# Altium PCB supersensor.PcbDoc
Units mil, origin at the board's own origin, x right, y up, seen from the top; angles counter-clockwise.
Board outline 1574.8 x 1574.8 mil, 2 copper layers (Top Layer, Bottom Layer); 41 components, 20 nets, 150 pads, 21 vias.
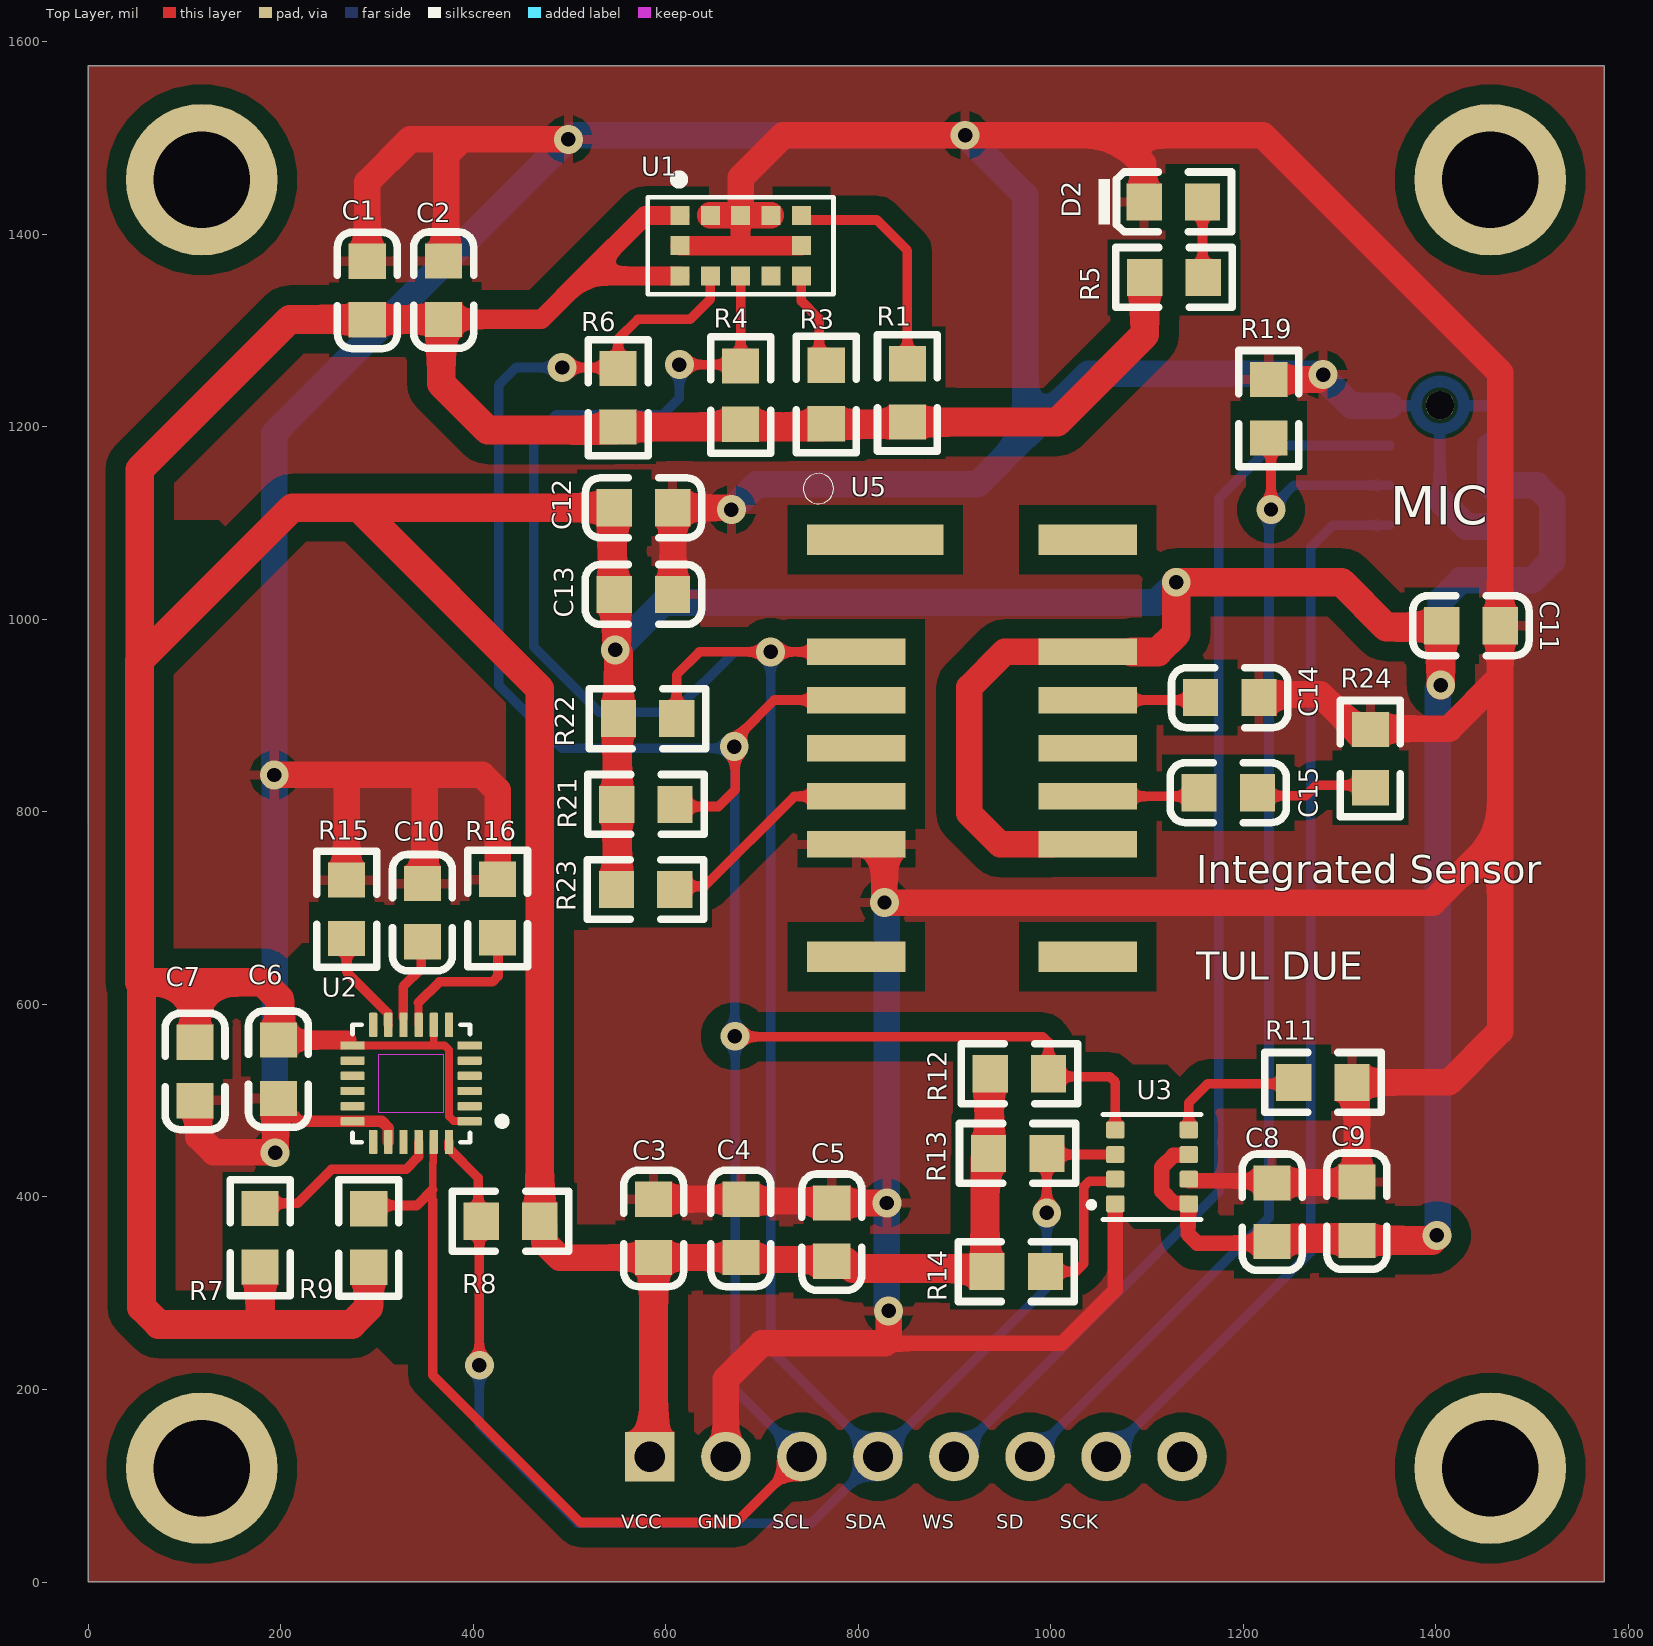
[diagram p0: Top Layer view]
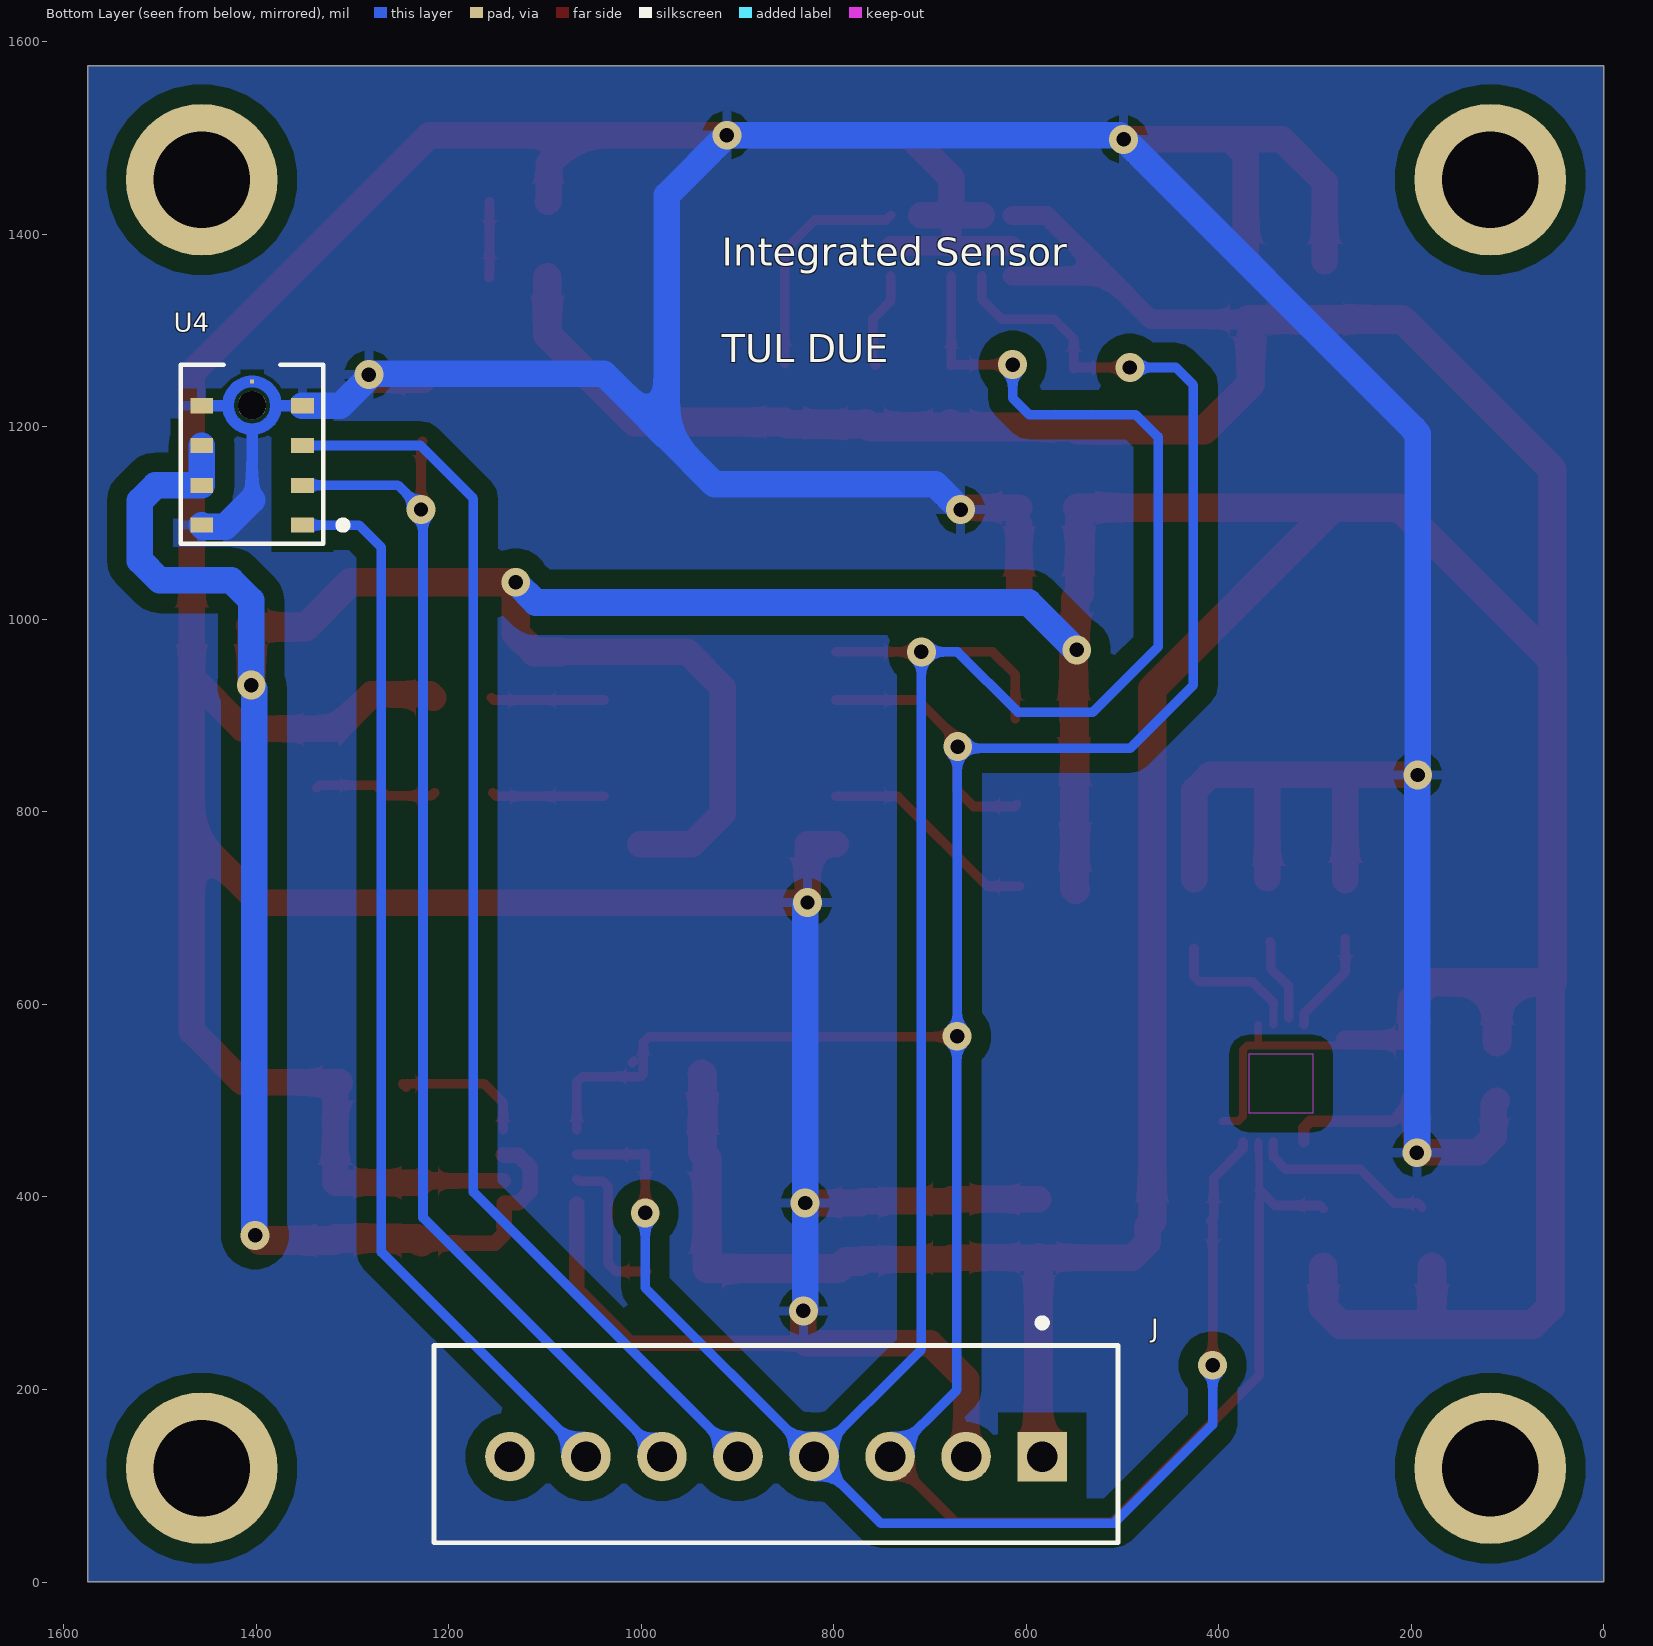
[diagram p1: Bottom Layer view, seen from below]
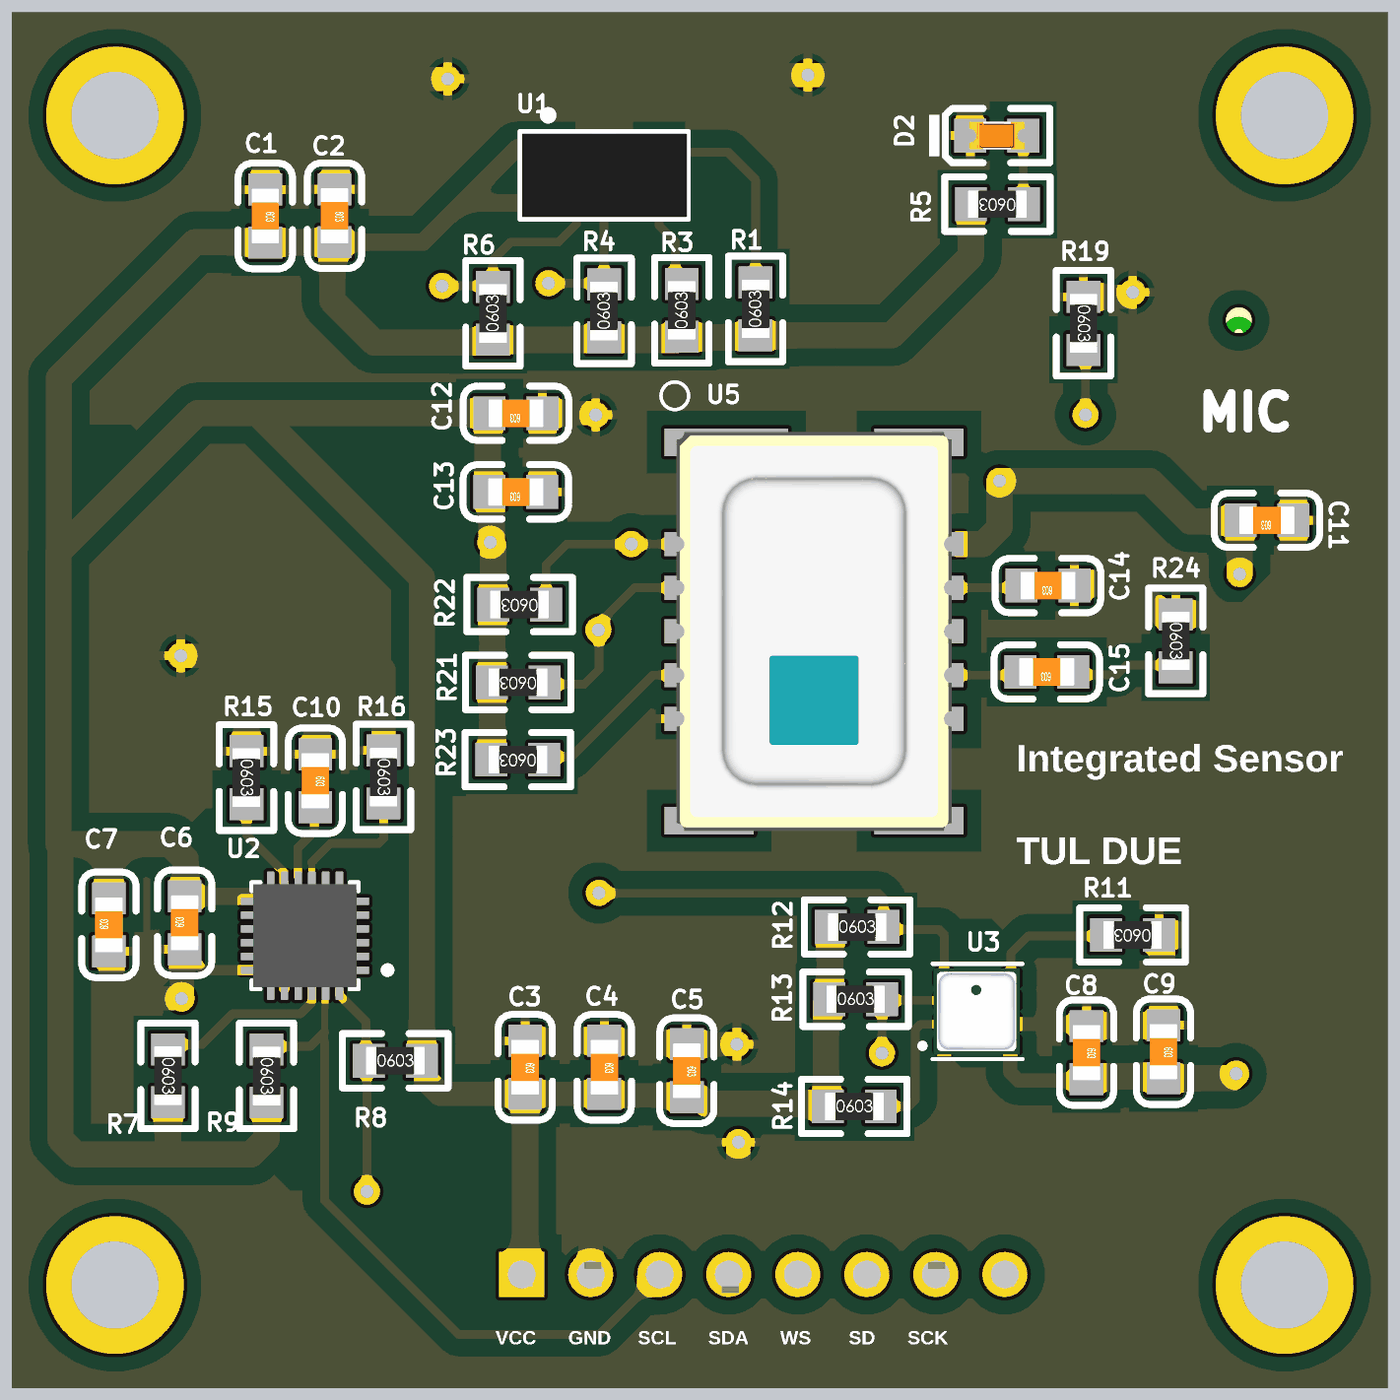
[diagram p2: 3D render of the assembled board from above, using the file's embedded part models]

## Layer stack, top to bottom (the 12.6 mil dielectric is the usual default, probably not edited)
Top Solder: solder mask 0.4, Solder Resist, Dk 3.5
Top Layer: signal copper 1.4
Dielectric 1: dielectric 12.6, FR-4, Dk 4.8
Bottom Layer: signal copper 1.4
Bottom Solder: solder mask 0.4, Solder Resist, Dk 3.5

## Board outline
0,0 0,1574.8 1574.8,1574.8 1574.8,0

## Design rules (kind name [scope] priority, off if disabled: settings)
Clearance [All] p1: gap=20 ignorepadtopadclearanceinfootprint=TRUE
PolygonConnect [All] p1: connectstyle=Relief reliefconductorwidth=10 reliefentries=4 polygonreliefangle="90 Angle" airgapwidth=10
RoutingVias [All] p1: holewidth=28 width=50 viastyle="Through Hole" minholewidth=28 minwidth=50 maxholewidth=28 maxwidth=50
SolderMaskExpansion [All] p1: expansion=4 istentingtop=FALSE
Width GND [InNet('GND')] p1: maxlimit=27.56 minlimit=27.56 preferedwidth=27.56 minimp=50.000000 maximp=50.000000 favimp=50.000000
Width VCC [InNet('VCC')] p2: maxlimit=30 minlimit=27.56 preferedwidth=30 toplayer_minwidth=30 bottomlayer_maxwidth=27.56 bottomlayer_prefwidth=27.56 minimp=50.000000 maximp=50.000000 favimp=50.000000
Width [All] p3: maxlimit=10 minlimit=10 preferedwidth=10
30 further rules are at their usual default settings.

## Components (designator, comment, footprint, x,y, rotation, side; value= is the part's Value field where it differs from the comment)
C1 "4.7uF" 0603_C 290.12,1341.62 r270 top
C2 "100nF" 0603_C 369.41,1341.91 r270 top
C3 "4.7uF" 0603_C 587.6,367.32 r270 top
C4 "10uF" 0603_C 678.15,367.32 r270 top
C5 "100nF" 0603_C 772.64,363.39 r270 top
C6 "10nF" 0603_C 197.83,532.68 r90 top
C7 "100nF" 0603_C 111.22,530.31 r90 top
C8 "1uF" 0603_C 1230.06,384.14 r270 top
C9 "100nF" 0603_C 1318.09,385.18 r270 top
C10 "100nF" 0603_C 347.4,695.28 r270 top
C11 "100nF" 0603_C 1436.59,993.39 r180 top
C12 "10uF" 0603_C 577.05,1115.89 r180 top
C13 "100nF" 0603_C 576.92,1025.84 r180 top
C14 "2.2uF" 0603_C 1185.98,918.66 r180 top
C15 "1uF" 0603_C 1184.49,819.92 r180 top
D2 "绿灯 0603" 0603_LED_S1 1127.44,1433.6 r0 top
J "Pin-8" Pin-8 860.08,130.24 r180 bottom
R1 "10KΩ" 0603_R 851.2,1235.26 r90 top
R3 "10KΩ" 0603_R 766.87,1233.61 r90 top
R4 "2.2KΩ" 0603_R 677.95,1232.98 r90 top
R5 "1KΩ" 0603_R 1128.07,1355.14 r180 top
R6 "2.2KΩ" 0603_R 550.71,1230.16 r90 top
R7 "10KΩ" 0603_R 178.79,357.61 r270 top
R8 "10KΩ" 0603_R 438.94,374.8 r0 top
R9 "10KΩ" 0603_R 291.62,357.39 r270 top
R11 "10KΩ" 0603_R 1282.76,518.89 r180 top
R12 "10KΩ" 0603_R 967.5,527.95 r0 top
R13 "10KΩ" 0603_R 965.77,445.19 r0 top
R14 "10KΩ" 0603_R 964.28,322.5 r0 top
R15 "10KΩ" 0603_R 268.66,698.86 r270 top
R16 "10KΩ" 0603_R 425.43,699.61 r270 top
R19 "100KΩ" 0603_R 1226.55,1218.81 r270 top
R21 "4.7KΩ" 0603_R 579.56,807.76 r180 top
R22 "4.7KΩ" 0603_R 581.26,896.89 r180 top
R23 "10KΩ" 0603_R 579.2,719.37 r180 top
R24 "20Ω" 0603_R 1332.13,855.29 r270 top
U1 "VL53L1X" VL53L1X 677.95,1388.11 r90 top
U2 "9250" MPU9250 335.63,517.91 r180 top
U3 "280" BME280 1105.31,431.22 r180 top
U4 "441" INMP441 1404.41,1171.47 r270 bottom
U5 "GRIDEYE" AMG8833 918.31,866.14 r270 top

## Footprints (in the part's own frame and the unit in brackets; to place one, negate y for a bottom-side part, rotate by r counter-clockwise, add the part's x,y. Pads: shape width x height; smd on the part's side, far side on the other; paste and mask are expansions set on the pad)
0603_C [mm]
  rect 0.93x0.98 smd: 1(-0.77,0) 2(0.77,0)
  silkscreen extent -1.53,-0.79 1.54,0.79, body extent -0.8,-0.4 0.8,0.4, height 0.3
0603_LED_S1 [mm]
  rect 0.93x0.98 smd: A(0.77,0) K(-0.77,0)
  silkscreen extent -1.97,-0.79 1.54,0.79, body extent -0.8,-0.4 0.8,0.4, height 0.6
0603_R [mm]
  rect 0.93x0.98 smd: 1(-0.77,0) 2(0.77,0)
  silkscreen extent -1.53,-0.79 1.54,0.79, body extent -0.85,-0.4 0.85,0.4, height 0.56
AMG8833 [mm]
  rect 0.8x3.6 smd: 1(-5.5,-2.55)
  rect 0.7x2.6 smd: 2(-2.54,-3.05) 3(-1.27,-3.05) 4(0,-3.05) 5(1.27,-3.05) 6(2.54,-3.05) 9(2.54,3.05) 10(1.27,3.05) 11(0,3.05) 12(-1.27,3.05) 13(-2.54,3.05)
  rect 0.8x2.6 smd: 7(5.5,-3.05) 8(5.5,3.05) 14(-5.5,3.05)
  silkscreen extent -7.25,-4.45 -6.45,-3.65, body extent -5.8,-4 5.8,4, height 4.3
BME280 [mm]
  rrect25% 0.49x0.45 smd: 1(0.97,0.975) 2(0.97,0.325) 3(0.97,-0.325) 4(0.97,-0.975) 5(-0.97,-0.975) 6(-0.97,-0.325) 7(-0.97,0.325) 8(-0.97,0.975)
  silkscreen extent -1.3,-1.39 1.65,1.39, body extent -1.22,-1.25 1.28,1.25, height 1
INMP441 [mm]
  rect 0.4x0.6 smd paste-1: 1(1.87,1.33) 2(0.82,1.33) 3(-0.23,1.33) 4(-1.28,1.33) 6(-1.28,-1.33) 7(-0.23,-1.33) 8(0.82,-1.33) 9(1.87,-1.33)
  rect 0.1x0.1 smd paste-1 mask+0: 5(-1.92,0)
  round 0.75 hole 0.75 unplated: ""(-1.29,0)
  Top Layer region: 243 vertices and 0 holes, not listed, extent -2.07,-0.78 -0.51,0.78
  silkscreen extent -2.36,-1.88 2.36,2.5, body extent -2.33,-1.88 2.39,1.88, height 1.05
MPU9250 [mm]
  rrect25% 0.64x0.22 smd: 1(-1.545,1) 2(-1.545,0.6) 3(-1.545,0.2) 4(-1.545,-0.2) 5(-1.545,-0.6) 6(-1.545,-1) 13(1.545,-1) 14(1.545,-0.6) 15(1.545,-0.2) 16(1.545,0.2) 17(1.545,0.6) 18(1.545,1)
  rrect25% 0.22x0.64 smd: 7(-1,-1.545) 8(-0.6,-1.545) 9(-0.2,-1.545) 10(0.2,-1.545) 11(0.6,-1.545) 12(1,-1.545) 19(1,1.545) 20(0.6,1.545) 21(0.2,1.545) 22(-0.2,1.545) 23(-0.6,1.545) 24(-1,1.545)
  Keep-Out Layer region: 0.85,-0.77 -0.85,-0.77 -0.85,0.77 0.85,0.77
  Keep-Out Layer region: 0.85,-0.77 -0.85,-0.77 -0.85,0.77 0.85,0.77
  silkscreen extent -2.5,-1.55 1.55,1.55, body extent -1.5,-1.5 1.5,1.5, height 1
Pin-8 [mm]
  rect 1.308x1.308 hole 0.8: 1(7.023,0)
  round 1.308 hole 0.8: 2(5.016,0) 3(3.01,0) 4(1.003,0) 5(-1.003,0) 6(-3.01,0) 7(-5.016,0) 8(-7.023,0)
  silkscreen extent -9.02,-2.27 9.02,3.63, body extent -9.04,-3.02 8.96,2.78, height 7
VL53L1X [mm]
  rect 0.5x0.5 smd: 1(0.8,1.6) 2(0.8,0.8) 3(0.8,0) 4(0.8,-0.8) 5(0.8,-1.6) 6(0,-1.6) 7(-0.8,-1.6) 8(-0.8,-0.8) 9(-0.8,0) 10(-0.8,0.8) 11(-0.8,1.6) 12(0,1.6)
  silkscreen extent -1.28,-2.45 1.87,2.45, body extent -1.2,-2.41 1.2,2.39, height 1.4

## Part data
C1 C3: library part "0603 4.7uF (475) 10% 16V", "贴片电容", Package=0603, SuppliersPartNumber=C19666
C2 C5 C7 C9 C10 C11 C13: library part "0603 100nF (104) 10% 50V", "贴片电容", Package=0603, SuppliersPartNumber=C14663
C4 C12: library part "0603 10uF (106) 10% 10V", "贴片电容", Package=0603, SuppliersPartNumber=C19702
C6: library part "0603 10nF (103) 10% 50V", "贴片电容", Package=0603, SuppliersPartNumber=C57112
C8 C15: library part "0603 1uF (105) 10% 50V", "贴片电容", Package=0603, SuppliersPartNumber=C15849
C14: library part "0603 2.2uF (225) 10% 16V", "贴片电容", Package=0603, SuppliersPartNumber=C23630
D2: library part "0603 绿灯", "发光二极管", Package=0603, SuppliersPartNumber=C72043
J: "Connector Header Through Hole 8 position 0.079 (2.00mm)", Package=None
R1 R3 R7 R8 R9 R11 R12 R13 R14 R15 R16 R23: library part "0603 10KΩ (1002) 1%", "贴片电阻", Package=0603, SuppliersPartNumber=C25804
R4 R6: library part "0603 2.2KΩ (2201) 1%", "贴片电阻", Package=0603, SuppliersPartNumber=C4190
R5: library part "0603 1KΩ (1001) 1%", "贴片电阻", Package=0603, SuppliersPartNumber=C21190
R19: library part "0603 100KΩ (1003) 1%", "贴片电阻", Package=0603, SuppliersPartNumber=C25803
R21 R22: library part "0603 4.7KΩ (4701) 1%", "贴片电阻", Package=0603, SuppliersPartNumber=C23162
R24: library part "0603 20Ω (20R0) 1%", "贴片电阻", Package=0603, SuppliersPartNumber=C22950
U1 U5: "IC"
U2: library part MPU9250, "IC"
U3: library part BME280, "IC"
U4: library part INMP441, "IC"

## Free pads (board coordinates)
  round 157.48 hole 100: 1(118.11,118.11) 2(1456.69,118.11) 3(1456.69,1456.69) 4(118.11,1456.69)

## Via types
v1: diameter 30, hole 15, Top Layer to Bottom Layer, 21 vias

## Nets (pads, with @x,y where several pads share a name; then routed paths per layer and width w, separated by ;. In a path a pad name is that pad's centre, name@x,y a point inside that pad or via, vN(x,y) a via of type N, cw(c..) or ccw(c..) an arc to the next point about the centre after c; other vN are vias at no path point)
GND: C1.1 C2.1 C3.1 C4.1 C5.1 C6.1 C7.1 C8.1 C9.1 C10.1 C11.1 C12.1 C13.1 C14.1 D2.K J.2 R11.1 R15.1 R16.1 R19.1 R24.1 U1.2 U1.3 U1.4 U1.6 U1.12 U2.18 U2.20 U3.1 U3.7 U4.4 U4.5 U4.6 U4.9 U5.6 | length 9260.3
  Top Layer w11.81: C6.1@196.65,501.18 219.29,478.54 U2.18 305.09,478.54 312.01,471.62 U2.20
  Top Layer w15.75: 699.94,248.01 1011.84,248.01 1067.13,303.3 U3.1 ; 828.13,251.49 831.6,251.49
  Top Layer w16: U3.7@1143.5,416.62 C8.1@1227.9,416.62
  Top Layer w20: U1.12 677.95,1388.11 ; U1.3 677.95,1388.11 ; U1.6 677.95,1388.11
  Top Layer w27.56: C7.1 114.72,496.51 114.72,462.55 130.86,446.41 193.82,446.41 v1(194.29,445.94) 194.76,446.41 194.76,499.29 C6.1@196.65,501.18 ; v1(193.48,838.28) 193.56,838.36 409.29,838.36 425.43,822.22 R16.1 ; R15.1 268.66,835.35 ; C1.1 290.12,1453.99 334.67,1498.53 388.06,1498.53 ; C10.1@349.68,730.96 349.68,832.39 ; C2.1@369.72,1371.55 371.92,1373.75 371.92,1482.39 388.06,1498.53 ; v1(499.02,1498.53) 388.06,1498.53 ; C3.1 C4.1 680.12,395.67 770.67,395.67 C5.1 v1(829.85,393.71) ; C13.1 607.54,1026.14 607.54,1098.68 C12.1@607.85,1098.99 ; C12.1 665.84,1115.89 667.76,1113.97 v1(668.42,1113.97) ; U1.2 U1.3 ; J.2 662.6,210.67 699.94,248.01 828.13,248.02 831.6,251.49 v1(831.6,281.64) ; U1.4 U1.3 ; U5.6 827.37,766.14 v1(827.37,705.88) 827.53,705.72 1396.77,705.72 1466.91,775.86 ; D2.K 1095.99,1434.74 1095.99,1473.4 1066.47,1502.92 ; C14.1 1219.77,922.13 1280.16,922.13 1315.93,886.37 1413.77,886.37 1466.91,939.5 ; R19.1 1277.29,1249.12 1282.35,1254.18 v1(1283.01,1254.18) ; C8.1@1227.9,416.62 C8.1 1230.57,414.98 1317.57,414.98 C9.1 1318.09,512.89 1313.07,517.91 R11.1 1413.58,518.89 1466.91,572.22 1466.91,775.86 ; U1.3 677.95,1458.58 722.29,1502.92 v1(911.11,1502.92) 1066.47,1502.92 ; 1066.47,1502.92 1220.22,1502.92 1466.91,1256.24 C11.1 1466.91,939.5 ; 1466.91,775.86 1466.91,939.5
  Bottom Layer w11.81: U4.4 1373.87,1221.86 ; 1404.31,1123.97 1404.31,1197.45 ; 1435.07,1221.86 U4.6
  Bottom Layer w27.56: v1@193.89,445.68 193.89,837.88 v1(193.48,838.28) 193.48,1192.9 197.63,1197.04 197.63,1197.7 502.84,1502.92 v1(911.11,1502.92) 973.59,1440.44 973.59,1189.76 ; v1(668.42,1113.97) 694.58,1140.12 923.95,1140.12 973.59,1189.76 ; v1(827.37,705.88) 827.37,705.21 829.85,702.73 v1(829.85,393.71) 829.85,284.04 831.6,282.3 v1(831.6,281.64) ; v1@1282.82,1253.72 1283.48,1253.06 1283.48,1250.94 1312.56,1221.86 U4.4 ; v1(1283.01,1254.18) 1282.54,1254.65 1280.82,1254.65 1280.37,1255.09 1038.92,1255.09 973.59,1189.76 ; 1404.31,1123.97 1432.04,1096.23 1455.16,1096.23 U4.9
IIC_SCL: J.3 R6.2 R9.1 R12.2 R21.1 U1.10 U2.23 U3.4 U5.3 | length 3196.1
  Top Layer w8: 358.02,396.45 358.02,407.62 358.02,435.07 358.5,435.56 358.5,445.7 358.92,446.12 358.92,456.76 U2.23
  Top Layer w10: R9.1 295.08,391.17 341.57,391.17 358.02,407.62 ; 358.02,396.45 358.02,215.06 511.33,61.75 673.09,61.75 J.3 ; v1(492.55,1261.57) 549.61,1261.57 R6.2 550.71,1291.35 571.05,1311.69 625.37,1311.69 646.46,1332.78 U1.10 ; R21.1 612.07,805.57 654.97,805.57 672.2,822.8 672.2,866.98 v1(671.37,867.81) 671.37,873.22 676.03,877.88 676.03,879.32 712.85,916.14 U5.3 ; v1@671.98,566.38 991.96,566.38 997.82,560.52 R12.2 1000.75,525.02 1061.27,525.02 1067.13,519.16 U3.4 ; R12.2@1007.45,541.46 R12.2@1009.24,539.67
  Bottom Layer w10: v1(492.55,1261.57) 444.73,1261.57 426.5,1243.34 426.5,931.82 492.36,865.95 669.51,865.95 v1(671.37,867.81) 671.67,867.51 671.67,567.43 672.2,566.9 672.2,199.61 J.3
  other v1: 671.98,566.9
IIC_SDA: J.4 R4.2 R8.1 R13.2 R22.1 U1.9 U2.24 U3.3 U5.2 | length 3261.1
  Top Layer w10: U2.24 375,450.16 405.39,419.76 405.39,378.03 R8.1 406.52,372.7 v1(406.52,225.13) ; R22.1 611.58,942.53 635.24,966.19 v1(709.1,966.19) ; v1(614.28,1264.61) R4.2@675.83,1264.61 ; R4.2@677.06,1265.84 R4.2@675.83,1264.61 ; U1.9 R4.2 676.63,1264.61 R4.2@675.83,1264.61 ; v1(709.1,966.19) U5.2 ; J.4 J.4@820.59,134.72 ; R13.2@995.82,445.46 R13.2 995.93,445.04 v1(995.93,383.38) ; R13.2@996.09,444.02 U3.3
  Bottom Layer w10: v1(406.52,225.13) 406.52,163.57 508.99,61.1 751.45,61.1 J.4 ; v1(614.28,1264.61) 614.28,1229.81 596.89,1212.42 486.25,1212.42 463.18,1189.36 463.18,971.43 530.98,903.63 608.85,903.63 671.41,966.19 v1(709.1,966.19) 709.1,241.73 J.4 ; v1(995.93,383.38) 995.93,305.58 J.4
Mic_SCK: J.7 U4.1 | length 1124
  Bottom Layer w10: J.7 1270.1,342.78 1270.1,1074.7 1293.25,1097.84 U4.1
Mic_SD: J.6 R19.2 U4.2 | length 1293.7
  Top Layer w10: R19.2@1227.27,1185.11 1228.88,1183.49 v1(1228.88,1114.07)
  Bottom Layer w10: J.6 1005.61,157.26 1226.86,378.51 1226.86,1113.32 1252.89,1139.35 1351.88,1139.35 U4.2
Mic_WS: J.5 U4.3 | length 1309.5
  Bottom Layer w10: J.5 1174.46,405.13 1174.46,1125.43 1229.55,1180.52 U4.3
NetC10_2: C10.2 U2.10 | length 86.9
  Top Layer w10: U2.10@327.34,586.34 327.34,618.52 346.33,637.51 346.33,663.89 C10.2
NetC14_2: C14.2 U5.12 | length 118.3
  Top Layer w10: U5.12 1153.15,916.14 C14.2
NetC15_1: C15.1 R24.2 | length 129.5
  Top Layer w10: C15.1 1218.16,816.56 1264.83,816.56 1275.98,827.72 1334.26,827.72 R24.2@1337.08,824.89
NetC15_2: C15.2 U5.10 | length 117.4
  Top Layer w10: U5.10 1150.39,816.14 C15.2
NetD2_A: D2.A R5.1 | length 78.7
  Top Layer w10: D2.A 1157.76,1355.77 R5.1
NetR1_2: R1.2 U1.5 | length 242.9
  Top Layer w10: U1.5 745.79,1414.76 819.45,1414.76 851.2,1383.01 R1.2
NetR3_2: R3.2 U1.7 | length 92.5
  Top Layer w10: U1.7 740.94,1330.57 759.52,1311.99 R3.2@759.52,1272.75 ; R3.2@756.46,1263.81 R3.2@757.44,1263.81
NetR7_1: R7.1 U2.22 | length 191.4
  Top Layer w10: R7.1@189.19,389.32 193.22,393.34 217.63,393.34 252.87,428.58 330.31,428.58 343.5,441.77 U2.22
NetR11_2: R11.2 U3.5 | length 142.4
  Top Layer w10: U3.5 1143.5,497.97 1163.06,517.53 R11.2@1244.17,517.53 ; R11.2@1244.17,513.79 R11.2@1247.91,517.53
NetR14_2: R14.2 U3.2 | length 159.1
  Top Layer w10: R14.2 1026.17,322.5 1034.2,330.53 1034.2,410.52 1040.06,416.38 1065.08,416.38 U3.2
NetR15_2: R15.2 U2.11 | length 107.8
  Top Layer w10: R15.2 268.66,633.75 311.34,591.08 311.34,579.41 U2.11
NetR16_2: R16.2 U2.9 | length 146.2
  Top Layer w8: 343.34,601.85 343.34,578.91 U2.9
  Top Layer w10: 343.34,601.85 364.98,623.49 420.05,623.49 425.91,629.35 R16.2@425.91,658.39
NetR23_1: R23.1 U5.5 | length 229.7
  Top Layer w10: R23.1@607.21,722.73 640.45,722.73 733.86,816.14 U5.5
VCC: C1.2 C2.2 C3.2 C4.2 C5.2 C6.2 C7.2 C8.2 C9.2 C11.2 C12.2 C13.2 J.1 R1.1 R3.1 R4.1 R5.2 R6.1 R7.2 R8.2 R9.2 R12.1 R13.1 R14.1 R21.2 R22.2 R23.2 U1.1 U1.11 U2.1 U2.8 U2.13 U3.6 U3.8 U4.7 U4.8 U5.9 U5.13 | length 8960
  Top Layer w8: U2.13 359.25,557.28 ; U2.8 359.25,557.28 ; U2.1 396.13,478.87 379.75,478.87 375.06,483.56 375.06,552.6 370.38,557.28 359.25,557.28
  Top Layer w16: J.1 J.1@587.6,134.25 ; U3.6 1142.65,443.16 1127.52,443.16 1115.38,431.02 1115.38,406.01 1127.69,393.69 1142.65,393.69 1142.65,361.46 1152.02,352.09 C8.2@1228.32,352.09
  Top Layer w19.68: C6.2 269.09,562.99
  Top Layer w20: C2.2 470.87,1311.6 515.88,1356.61 ; U1.11 515.88,1356.61 ; U1.1 578.88,1419.61 515.88,1356.61
  Top Layer w27.56: R8.2 473.78,370.28 473.78,353.15 489.92,337.01 C3.2 C4.2 680.12,335.04 770.67,335.04 C5.2 ; C12.2@546.64,1115.8 C12.2 ; R4.1@677.34,1202.05 R4.1 ; U5.9@1000.98,766.14 947.64,766.14 915.39,798.39 915.39,929.33 952.2,966.14 U5.13 U5.13@1083.86,966.14 ; C8.2@1228.32,352.09 C8.2
  Top Layer w30: C7.2 111.22,623 ; R7.2 178.79,271.97 183.08,267.68 ; C6.2 199.03,564.19 199.03,605.43 181.46,623 111.22,623 ; 283.64,1113.56 469.25,927.94 R8.2 ; R9.2 291.62,285.25 274.04,267.68 183.08,267.68 ; C2.2@366.91,1295.42 366.91,1244.87 415.25,1196.54 547.4,1196.54 R6.1 762.43,1199.84 765.88,1203.3 R3.1 767.56,1202.61 848.86,1202.61 R1.1 1006.85,1204.95 1097.75,1295.85 R5.2 ; C2.2 369.26,1311.45 290.27,1311.45 C1.2 289.83,1311.6 209.52,1311.6 53.75,1155.83 53.75,957.34 ; C12.2 C12.2@544.66,1115.89 ; R23.2 549.91,720.4 549.91,895.86 R22.2 550.95,964.96 v1(547.72,968.18) 549.2,969.67 549.2,1021.55 544.66,1026.09 C12.2@544.66,1115.89 ; J.1@587.6,134.25 C3.2 ; R4.1 R4.1@679.01,1203.72 ; C5.2 787.12,333.07 794.5,325.69 931.76,325.69 931.76,440.51 935.45,444.21 R13.1 936.32,446.06 936.32,527.08 R12.1 ; U5.13@1083.86,966.14 1111.45,966.14 1130.49,985.19 v1(1130.49,1038.49) 1302.21,1038.49 1348.78,991.92 C11.2@1392.27,991.92 ; C8.2 1233.22,356.99 1317.81,356.99 C9.2@1319.02,355.79 ; C9.2@1318.64,354.86 1396.04,354.86 v1(1401.22,360.05) ; v1(1405.2,931.71) 1405.2,992.32 C11.2 ; 53.75,957.34 53.58,957.17 53.58,623 55.7,623 ; 53.75,957.34 212.3,1115.89 C12.2@544.66,1115.89 ; 55.7,623 111.22,623 ; 55.7,623 55.7,285.25 73.27,267.68 183.08,267.68
  Bottom Layer w27.56: v1(547.72,968.18) 548.38,968.18 597.69,1017.49 1109.49,1017.49 v1(1130.49,1038.49) ; v1@1402.15,360.97 1402.15,927.99 1405.2,931.05 v1(1405.2,931.71) 1405.2,1019.67 1426.12,1040.59 1500.45,1040.59 1520.95,1061.09 1520.95,1123.04 1504.81,1139.18 U4.8 U4.7
pads on no net: J.8 U1.8 U2.2 U2.3 U2.4 U2.5 U2.6 U2.7 U2.12 U2.14 U2.15 U2.16 U2.17 U2.19 U2.21 U4. U5.1 U5.4 U5.7 U5.8 U5.11 U5.14

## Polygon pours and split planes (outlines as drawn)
GND on Bottom Layer "GND_L02_P001" (solid, remove dead copper, pour order 1): 0,1574.8 0,0 1574.8,0 1574.8,1574.8
GND on Top Layer "GND_L01_P000" (solid, remove dead copper, pour order 0): 0,-0.1 0.1,0 1574.8,0 1574.8,1574.8 1574.79,1574.8 -0.01,1574.8

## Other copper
Top Layer:
  pour cut-out: 203.8,638.1 210.3,638.1 228.9,619.5 234.6,625.2 234.6,663.9 222.36,663.9 206.42,647.96
  pour cut-out: 77.1,1103.1 136,1103.1 148.8,1090.3 96.2,1037.7 96.2,1033.3 90.4,1033.3 75.6,1048.1 75.6,1104.1
  pour cut-out: 1085.15,537.18 1121.22,537.18 1142.1,516.3 1125.1,499.3 1125.1,460.1 1113.2,460.1 1092.9,439.8 1085.15,447.55
  pour cut-out: 1080.9,395.8 1080.9,376.26 1079.32,374.69 1087.01,367 1124.3,367 1124.3,371.1 1095.2,400.2 1091.2,396.2 1081.1,396.2
  pour cut-out: 306.4,267.9 337.6,299.1 345.6,291.1 345.6,226.3 318,226.3 290.4,253.9 304.8,268.3 304.8,268.7
  pour cut-out: 364.3,1091.5 514.3,1091.5 519.7,1086.1 519.7,677.5 500.5,677.5 496.6,673.6 493.5,676.7 493.5,939.9 353.5,1079.9 362,1088.4 362,1093

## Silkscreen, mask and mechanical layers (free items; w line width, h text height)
Top Overlay:
  text "MIC" at 1353,1098.1 h40
  text "Integrated Sensor  /  / TUL DUE" at 1151.4,615.8 h50
  text "VCC      GND     SCL      SDA      WS       SD      SCK" at 553.7,50.29 h25
Bottom Overlay:
  text "Integrated Sensor  /  / TUL DUE" at 916.6,1257.3 h50
Mechanical 1:
  the board outline again, w10

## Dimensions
0,0 to 1574.8,0 on Mechanical 1
0,1574.8 to 0,0 on Mechanical 1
